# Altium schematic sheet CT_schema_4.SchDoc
size 395 x 205 mm
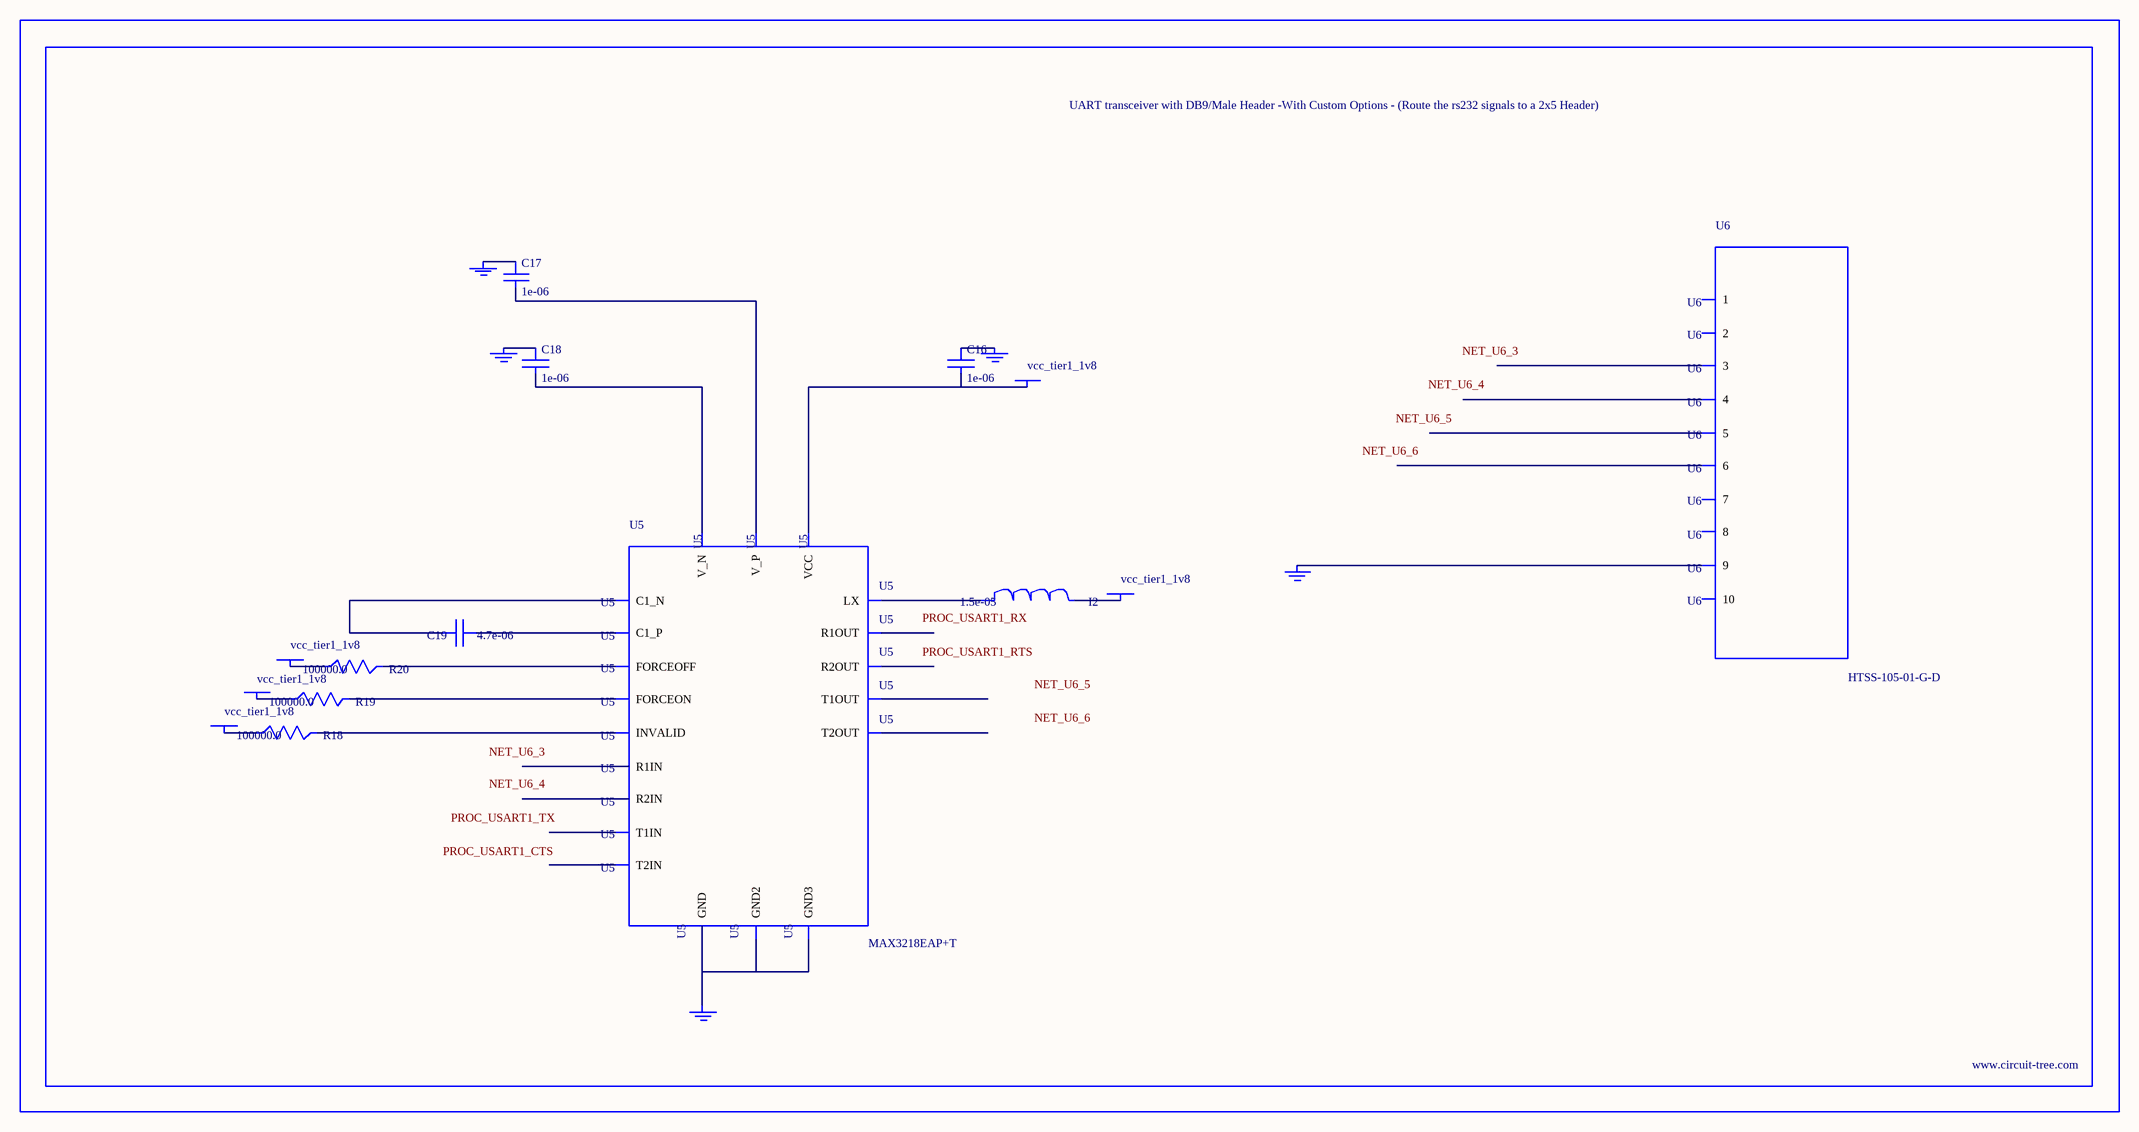
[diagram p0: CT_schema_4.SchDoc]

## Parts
BORDER3  (no value)
C16  1e-06  [C0603]
C17  1e-06  [C0603]
C18  1e-06  [C0603]
C19  4.7e-06  [C0805]
GND_INSTANCE_3_0  (no value)
GND_INSTANCE_3_1  (no value)
GND_INSTANCE_3_2  (no value)
GND_INSTANCE_3_3  (no value)
GND_INSTANCE_3_4  (no value)
I2  1.5e-05  [L1210]
POWER_INSTANCE_3_0  vcc_tier1_1v8
POWER_INSTANCE_3_1  vcc_tier1_1v8
POWER_INSTANCE_3_2  vcc_tier1_1v8
POWER_INSTANCE_3_3  vcc_tier1_1v8
POWER_INSTANCE_3_4  vcc_tier1_1v8
R18  100000.0  [R0603]
R19  100000.0  [R0603]
R20  100000.0  [R0603]
U5  MAX3218EAP+T  [SSOP-20]
U6  HTSS-105-01-G-D  [HTSS-105-01-G-D]

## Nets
NetC16_1: C16.1 GND_INSTANCE_3_0.0(GND)
NetC16_2: C16.2 POWER_INSTANCE_3_4.0(PWR) U5.6(VCC)
NetC17_1: C17.1 GND_INSTANCE_3_2.0(GND)
NetC17_2: C17.2 U5.19(V_P)
NetC18_1: C18.1 GND_INSTANCE_3_1.0(GND)
NetC18_2: C18.2 U5.15(V_N)
NetC19_1: C19.1 U5.18(C1_P)
NetC19_2: C19.2 U5.16(C1_N)
NetGND_INSTANCE_3_3_0: GND_INSTANCE_3_3.0(GND) U5.5(GND) U5.17(GND2) U5.20(GND3)
NetGND_INSTANCE_3_4_0: GND_INSTANCE_3_4.0(GND) U6.9
NetI2_1: I2.1 U5.1(LX)
NetI2_2: I2.2 POWER_INSTANCE_3_0.0(PWR)
NetPOWER_INSTANCE_3_1_0: POWER_INSTANCE_3_1.0(PWR) R18.1
NetPOWER_INSTANCE_3_2_0: POWER_INSTANCE_3_2.0(PWR) R19.1
NetPOWER_INSTANCE_3_3_0: POWER_INSTANCE_3_3.0(PWR) R20.1
NetR18_2: R18.2 U5.2(INVALID)
NetR19_2: R19.2 U5.3(FORCEON)
NetR20_2: R20.2 U5.4(FORCEOFF)

Not connected (* = marked no-connect by the designer): U5 7(T1IN) 8(T2IN) 9(R1OUT) 10(R2OUT) 11(R2IN) 12(R1IN) 13(T2OUT) 14(T1OUT); U6 1 2 3 4 5 6 7 8 10

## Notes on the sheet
- Labels drawn without touching a wire or pin: NET_U6_3, NET_U6_4, NET_U6_5, NET_U6_6, PROC_USART1_CTS, PROC_USART1_RTS, PROC_USART1_RX, PROC_USART1_TX

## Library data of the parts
BORDER3 = BORDER_PAGE3
C16-C18 = C0603C105K3RACTU
C19 = C0805C475K4RACTU
GND_INSTANCE_3_0-GND_INSTANCE_3_4 = GND
I2 = L1210R150MDWIT
POWER_INSTANCE_3_0-POWER_INSTANCE_3_4 = PWR
R18-R20 = RC0603JR-07100KL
